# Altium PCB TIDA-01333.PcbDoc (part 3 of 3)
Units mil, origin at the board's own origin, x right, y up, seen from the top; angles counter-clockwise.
Board outline 6250 x 2150 mil, 4 copper layers (Top Layer, GND, VDD, Bottom Layer), stack 61.6 mil thick; 242 components, 144 nets, 711 pads, 252 vias.
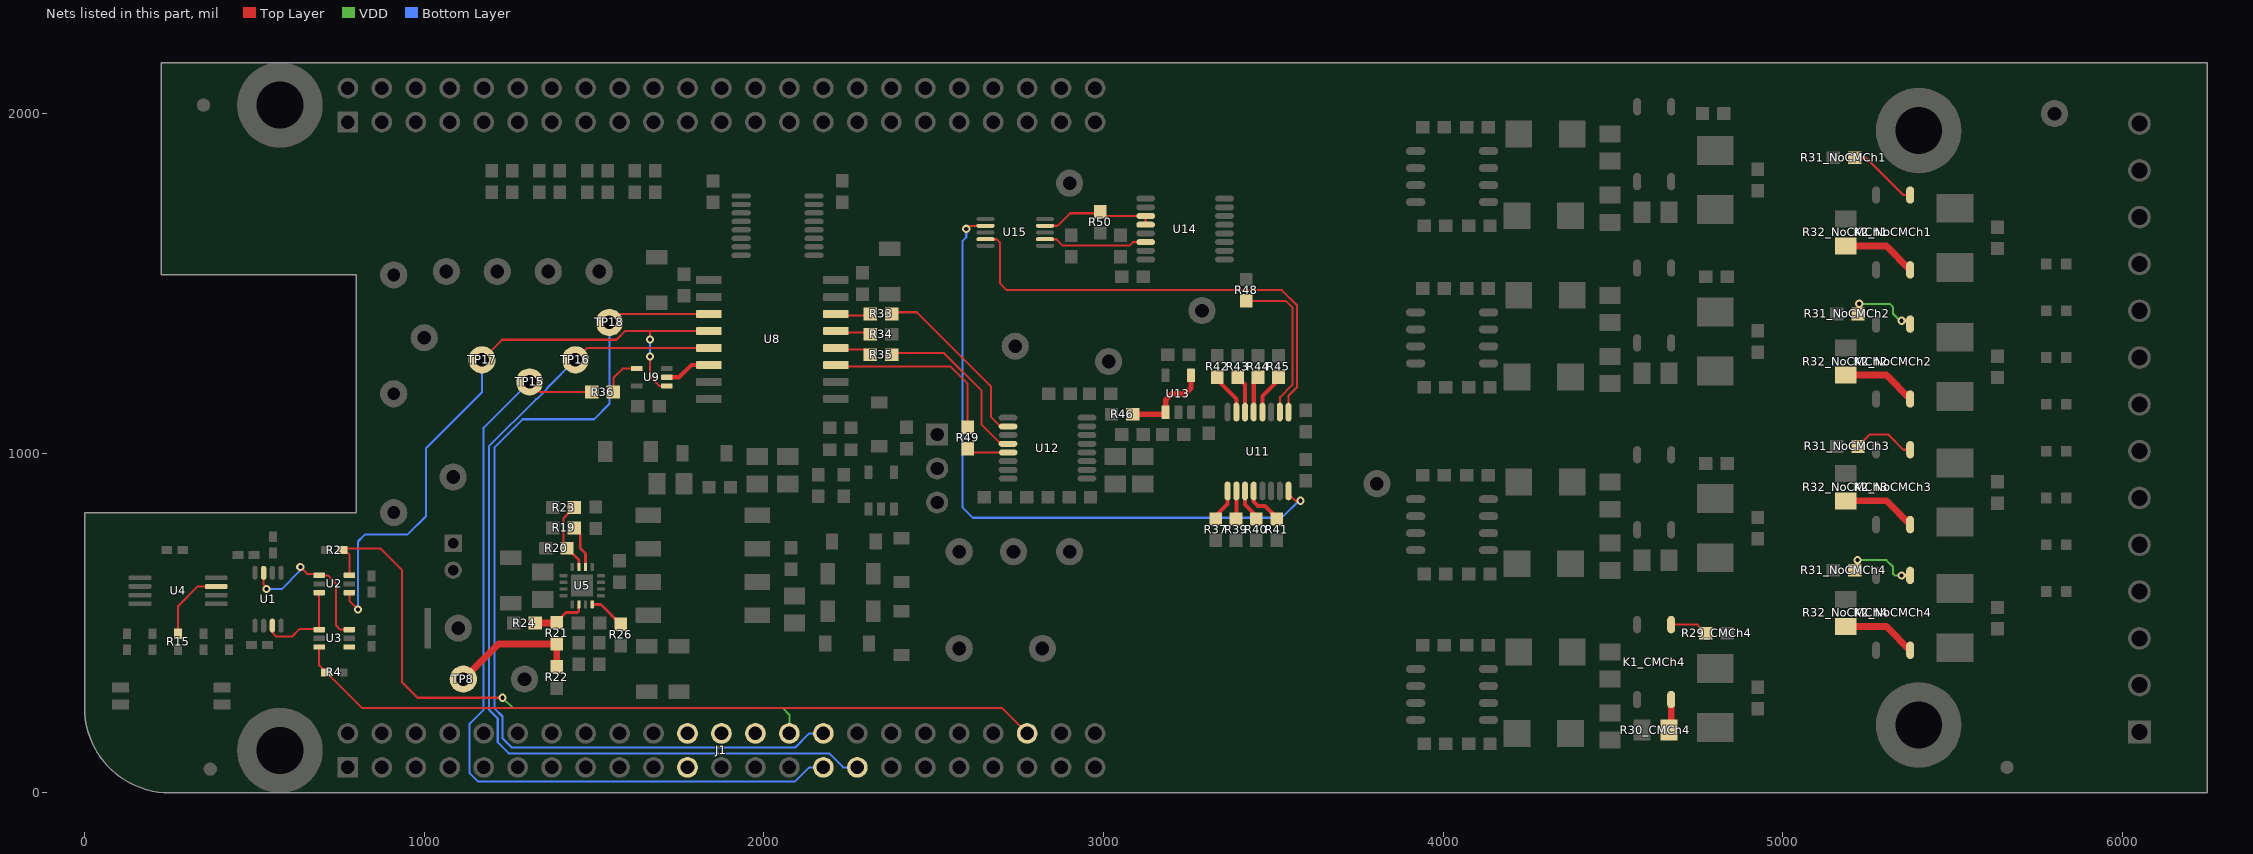
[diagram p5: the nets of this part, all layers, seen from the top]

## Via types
v1: diameter 24, hole 12, Top Layer to Bottom Layer, 210 vias
v2: diameter 39.37, hole 19.68, Top Layer to Bottom Layer, 24 vias
v3: diameter 32, hole 20, Top Layer to Bottom Layer, 17 vias
v4: diameter 19.68, hole 7.87, Top Layer to Bottom Layer, 1 vias

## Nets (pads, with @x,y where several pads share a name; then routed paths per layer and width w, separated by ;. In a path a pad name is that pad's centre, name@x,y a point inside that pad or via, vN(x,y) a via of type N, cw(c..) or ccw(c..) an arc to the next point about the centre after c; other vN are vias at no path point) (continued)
NetK1_CMCh4_1: K1_CMCh4.1 R29_CMCh4.1 | length 112.7
  Top Layer w6: K1_CMCh4.1@4671.26,495.24 4748.27,495.24 R29_CMCh4.1@4773.5,470
NetK1_CMCh4_4: K1_CMCh4.4 R30_CMCh4.2 | length 93.9
  Top Layer w20: R30_CMCh4.2@4661.26,185 4671.26,195 K1_CMCh4.4@4671.26,274.76
NetK2_NoCMCh1_1: K2_NoCMCh1.1 R31_NoCMCh1.1 | length 209
  Top Layer w6: R31_NoCMCh1.1@5211.5,1870 5245,1870 5354.76,1760.24 K2_NoCMCh1.1@5375,1760.24
NetK2_NoCMCh1_4: K2_NoCMCh1.4 R32_NoCMCh1.2 | length 219.1
  Top Layer w20: R32_NoCMCh1.2@5185,1610 5304.76,1610 K2_NoCMCh1.4@5375,1539.76
NetK2_NoCMCh2_1: K2_NoCMCh2.1 R31_NoCMCh2.1 | length 217.9
  Top Layer w6: R31_NoCMCh2.1@5221.5,1410 5221.5,1436.5 v1(5225,1440) ; v1(5350,1390) 5365.24,1390 K2_NoCMCh2.1@5375,1380.24
  VDD w6: v1(5225,1440) 5315,1440 5325,1430 5325,1410 5345,1390 v1(5350,1390)
NetK2_NoCMCh2_4: K2_NoCMCh2.4 R32_NoCMCh2.2 | length 219.1
  Top Layer w20: R32_NoCMCh2.2@5185,1230 5304.76,1230 K2_NoCMCh2.4@5375,1159.76
NetK2_NoCMCh3_1: K2_NoCMCh3.1 R31_NoCMCh3.1 | length 186.5
  Top Layer w6: R31_NoCMCh3.1@5221.5,1020 5256.5,1055 5310,1055 5354.76,1010.24 K2_NoCMCh3.1@5375,1010.24
NetK2_NoCMCh3_4: K2_NoCMCh3.4 R32_NoCMCh3.2 | length 219.1
  Top Layer w20: R32_NoCMCh3.2@5185,860 5304.76,860 K2_NoCMCh3.4@5375,789.76
NetK2_NoCMCh4_1: K2_NoCMCh4.1 R31_NoCMCh4.1 | length 219
  Top Layer w6: R31_NoCMCh4.1@5211.5,655 5220,663.5 v1(5220,685) ; v1(5350,640) 5374.76,640 K2_NoCMCh4.1@5375,640.24
  VDD w6: v1(5220,685) 5305,685 5325,665 5325,645 5330,640 v1(5350,640)
NetK2_NoCMCh4_4: K2_NoCMCh4.4 R32_NoCMCh4.2 | length 219.1
  Top Layer w20: R32_NoCMCh4.2@5185,490 5304.76,490 K2_NoCMCh4.4@5375,419.76
NetR15_2: R15.2 U4.3 | length 217.5
  Top Layer w6: R15.2@275.01,468.64 275.01,550.01 332.8,607.8 U4.3@387.2,607.8
NetR19_1: R19.1 U5.14 | length 129.1
  Top Layer w8: R19.1@1440.4,780 1458.9,761.5 1458.9,720.43 1474.84,704.49 U5.14@1474.84,665.12
NetR20_1: R20.1 R23.2 U5.15 | length 206.6
  Top Layer w6: R20.1@1420.4,720 1410,730.4 1410,808.5 R23.2@1441.5,840
  Top Layer w8: R20.1@1420.4,720 1455.16,685.24 U5.15@1455.16,665.12
NetR21_1: R21.1 R22.1 TP8.1 | length 384.9
  Top Layer w20: TP8.1@1115,335 1218.5,438.5 R21.1@1390,438.5 R22.1@1390,371.5
NetR21_2: R21.2 R24.2 U5.6 | length 162.9
  Top Layer w8: R21.2@1388.9,502.99 1417.11,531.2 1451.2,531.2 1455.16,535.16 U5.6@1455.16,554.88
  Top Layer w20: R24.2@1326.5,500 1385.91,500 R21.2@1388.9,502.99
NetR26_2: R26.2 U5.8 | length 108.3
  Top Layer w8: U5.8@1494.53,554.88 1519.96,554.88 R26.2@1578.55,496.3
NetR33_1: R33.1 U8.14 | length 107.7
  Top Layer w6: U8.14@2212.01,1410 2217.01,1405 R33.1@2303.5,1405 ; R33.1@2303.5,1400 R33.1@2313.5,1410
NetR34_1: R34.1 U8.13 | length 103.6
  Top Layer w6: U8.13@2212.01,1360 2217.01,1355 R34.1@2313.5,1355
NetR35_1: R35.1 U8.12 | length 107.7
  Top Layer w6: U8.12@2212.01,1310 2217.01,1305 R35.1@2303.5,1305 ; R35.1@2303.5,1300 R35.1@2313.5,1290
NetR36_2: R36.2 U9.4 | length 122.2
  Top Layer w6: R36.2@1556.5,1180 1556.5,1221.5 1584.27,1249.27 U9.4@1625.71,1249.27
NetR37_1: R37.1 U11.9 | length 97
  Top Layer w12: R37.1@3330,806.5 3330,815 3365.43,850.43 U11.9@3365.43,888.86
NetR39_1: R39.1 U11.10 | length 82.8
  Top Layer w12: R39.1@3390,806.5 3391.02,807.52 U11.10@3391.02,888.86
NetR40_1: R40.1 U11.11 | length 96.2
  Top Layer w12: U11.11@3416.61,888.86 3416.61,848.39 3450,815 R40.1@3450,806.5
NetR41_1: R41.1 U11.12 | length 122.2
  Top Layer w12: U11.12@3442.2,888.86 3442.2,857.8 3455,845 3475,845 3510,810 R41.1@3510,806.5
NetR42_1: R42.1 U11.7 | length 125.6
  Top Layer w12: R42.1@3335,1223.5 3335,1215 3391.02,1158.98 U11.7@3391.02,1121.14
NetR43_1: R43.1 U11.6 | length 111.3
  Top Layer w12: R43.1@3395,1223.5 3416.61,1201.89 U11.6@3416.61,1121.14
NetR44_1: R44.1 U11.5 | length 107.7
  Top Layer w12: U11.5@3442.2,1121.14 3442.2,1210.71 R44.1@3455,1223.5
NetR45_1: R45.1 U11.4 | length 121.9
  Top Layer w12: U11.4@3467.8,1121.14 3467.8,1167.8 3515,1215 R45.1@3515,1223.5
NetR46_2: R46.2 U13.1 U13.4 | length 255.8
  Top Layer w16: R46.2@3091.5,1115 3176.73,1115 U13.1@3182.6,1120.87 3182.6,1157.28 3200.31,1175 3239.68,1175 3257.4,1192.72 U13.4@3257.4,1229.13
NetR48_1: R48.1 U11.2 | length 468.9
  Top Layer w6: R48.1@3420,1448.5 3536.88,1448.5 3556.13,1429.25 3556.13,1201.13 3520,1165 3520,1120.39 U11.2@3519.29,1119.68
NetR49_2: R49.2 U12.13 | length 123.5
  Top Layer w6: R49.2@2600,1013.5 2611.3,1002.2 U12.13@2718.86,1002.2
NetR50_1: R50.1 U14.11 U14.12 U15.9 | length 333.4
  Top Layer w6: U15.9@2827.6,1669.69 2864.69,1669.69 2901.5,1706.5 R50.1@2985,1706.5 ; R50.1@2990,1701.5 2993.11,1698.39 U14.11@3123.86,1698.39 U14.12@3123.86,1672.8
NetU1_3: U1.3 U2.3 U3.1 | length 282.2
  Top Layer w6: U1.3@552.8,492.37 552.8,472.33 565,460.13 610.58,460.13 633.45,483 688.46,483 690.72,480.73 U2.3@690.72,589.52
NetU1_7: U1.7 U2.1 U3.6 | length 478.7
  Top Layer w6: U1.7@527.2,647.76 527.2,612.8 535,605 v1(535,600) ; v1(635,665) 655.13,644.87 690.71,644.87 U2.1@690.71,640.59 715.49,640.61 740.02,616.08 740.02,493.62 753.03,480.61 U3.6@779.31,480.61
  Bottom Layer w6: v1(535,600) 579.98,600 635,655.01 v1(635,665)
NetU8_6: U8.6 U9.2 | length 138.7
  Top Layer w12: U9.2@1714.29,1223.68 1750,1223.68 1786.32,1260 U8.6@1837.99,1260
NetU11_1: U11.1 U15.4 | length 1395
  Top Layer w6: U15.4@2652.09,1629.68 2652.09,1630 2685,1630 2695,1620 2695,1500 2715,1480 3525,1480 3570,1435 3570,1195 3544.88,1169.88 U11.1@3544.88,1119.68
NetU11_16: U11.16 U15.2 | length 1958.5
  Top Layer w6: v1(2595.75,1660.75) 2604.06,1669.06 U15.2@2652.09,1669.06 ; U11.16@3545,880 3565,860 v1(3580,860)
  Bottom Layer w6: v1(2595.75,1660.75) 2595.75,1635.75 2585,1625 2585,840 2615,810 3525,810 v1@3580,865
NetU14_14: U14.14 U15.7 | length 308.3
  Top Layer w6: U15.7@2827.91,1630 2861.18,1630 2880.24,1610.94 3075.94,1610.94 3086.61,1621.61 U14.14@3123.86,1621.61
SCLK_ISO: R35.2 U12.12 | length 532.3
  Top Layer w6: R35.2@2376.5,1295 2530,1295 2640,1185 2640,1085.64 2691.98,1033.65 2713,1033.65 U12.12@2718.86,1027.8 U12.12@2697.84,1027.8
SDI_ISO: R33.2 U12.10 | length 534.3
  Top Layer w6: R33.2@2376.5,1415 2450,1415 2668.87,1196.13 2668.87,1106.13 2696.02,1078.98 U12.10@2718.86,1078.98
SDO1_ISO: R49.1 U8.11 | length 539.3
  Top Layer w6: U8.11@2212.01,1260 2217.01,1255 2550,1255 2600,1205 R49.1@2600,1076.5
SPI_A: J1.28 R2.2 U2.6 | length 1834.5
  Top Layer w6: R2.2@766.51,715.01 779.31,702.22 U2.6@779.29,640.59 ; R2.2@771.51,720.01 869.98,720.01 935,655 935,325 980,280 v1(1230,280)
  VDD w6: v1(1230,280) 1260,250 2055,250 2075,230 J1.28@2075,175
SPI_B: J1.42 R4.2 U3.3 | length 2228.2
  Top Layer w6: U3.3@695.72,424.42 U3.3@690.72,429.42 690.72,375.65 R4.2@711.38,355 816.38,250 2700,250 J1.42@2775,175
SPI_CLK: J1.31 TP16.1 U8.5 | length 2740.7
  Top Layer w6: TP16.1@1445,1275 1480,1310 U8.5@1837.99,1310
  Bottom Layer w6: TP16.1@1445,1275 1445,1274.62 1360.87,1190.49 1360.87,1188.93 1331.07,1159.13 1329.51,1159.13 1190.38,1020 1190,1020 1190,245.38 1216.39,218.99 1216.39,148.61 1248.61,116.39 2192.14,116.39 2233.53,75 J1.31@2275,75
SPI_CSA: TP17.1 U2.4 U8.4 U9.1 | length 1918.1
  Top Layer w6: U2.4@779.29,589.41 779.29,565.71 v1(805,540) ; TP17.1@1170,1275 1229.13,1334.13 1566.07,1334.13 1591.95,1360 1665,1360 ; v1(1665,1285) 1665,1225 1691.91,1198.09 U9.1@1714.29,1198.09 ; v1(1665,1335) 1665,1360 ; U8.4@1837.99,1360 1665,1360
  Bottom Layer w6: v1(805,540) 805,740 825,760 950,760 1005,815 1005,1015 1170,1180 TP17.1@1170,1275 ; v1(1665,1285) v1(1665,1335)
SPI_CSB: U3.4
SPI_MISO: J1.29 R36.1 TP15.1 | length 2489.7
  Top Layer w6: TP15.1@1310,1210 1340,1180 R36.1@1493.5,1180
  Bottom Layer w6: TP15.1@1310,1210 1175,1075 1175,245 1133.61,203.61 1133.61,57.86 1157.86,33.61 2092.14,33.61 2133.53,75 J1.29@2175,75
SPI_MOSI: J1.30 TP18.1 U8.3 | length 2773
  Top Layer w6: TP18.1@1545,1385 1570,1410 U8.3@1837.99,1410
  Bottom Layer w6: TP18.1@1545,1385 1545,1145 1500,1100 1290,1100 1207.13,1017.13 1207.13,247.87 1230.26,224.74 1230.26,161.21 1257.86,133.61 2092.14,133.61 2133.53,175 J1.30@2175,175
UART_RXD1: J1.26
UART_RXD2: J1.22
UART_TXD1: J1.24
UART_TXD2: J1.21
pads on no net: FID1.1 FID2.1 FID3.1 J1.9 J1.10 J1.11 J1.12 J1.13 J1.14 J1.15 J1.16 J1.17 J1.18 J1.23 J1.25 J1.27 J1.32 J1.33 J1.34 J1.35 J1.36 J1.37 J1.38 J1.39 J1.40 J1.41 J2.3 J2.4 J2.5 J2.6 J2.7 J2.8 J2.9 J2.10 J2.13 J2.14 J2.19 J2.20 J2.21 J2.22 J2.23 J2.24 J2.25 J2.26 J2.31 J2.32 J2.33 J2.34 J2.35 J2.36 J2.37 J2.38 J2.39 J2.40 J2.41 J2.42 J2.43 J2.44 J2.45 J2.46 MH1.1 MH2.1 MH3.1 MH4.1 SH-J1.0 T1.3 U5.17@1465,610 U7_CMCh1.8 U7_CMCh2.8 U7_CMCh3.8 U7_CMCh4.8 U10.7 U12.14 U12.15 U14.9
copper on no net: | length 103920.8
  Top Layer w1: 10399.86,6070.32 10499.54,6170 10619.54,6290 10739.54,6410 10859.54,6530 10979.54,6650 11099.54,6770 11219.54,6890 11339.54,7010 11459.54,7130 11519.54,7190 ; 10399.86,6130.32 10439.54,6170 10559.54,6290 10679.54,6410 10799.54,6530 10919.54,6650 11039.54,6770 11159.54,6890 11279.54,7010 11399.54,7130 11519.54,7250 ; 10399.86,6190.32 10499.54,6290 10619.54,6410 10739.54,6530 10859.54,6650 10979.54,6770 11099.54,6890 11219.54,7010 11339.54,7130 11459.54,7250 11519.54,7310 ; 10399.86,6250.32 10439.54,6290 10559.54,6410 10679.54,6530 10799.54,6650 10919.54,6770 11039.54,6890 11159.54,7010 11279.54,7130 11399.54,7250 11519.54,7370 ; 10399.86,6310.32 10499.54,6410 10619.54,6530 10739.54,6650 10859.54,6770 10979.54,6890 11099.54,7010 11219.54,7130 11339.54,7250 11459.54,7370 ; 10399.86,6370.32 10439.54,6410 10559.54,6530 10679.54,6650 10799.54,6770 10919.54,6890 11039.54,7010 11159.54,7130 11279.54,7250 11399.54,7370 ; 10399.86,6430.32 10499.54,6530 10619.54,6650 10739.54,6770 10859.54,6890 10979.54,7010 11099.54,7130 11219.54,7250 11339.54,7370 ; 10399.86,6490.32 10439.54,6530 10559.54,6650 10679.54,6770 10799.54,6890 10919.54,7010 11039.54,7130 11159.54,7250 11279.54,7370 ; 10399.86,6550.32 10499.54,6650 10619.54,6770 10739.54,6890 10859.54,7010 10979.54,7130 11099.54,7250 11219.54,7370 ; 10399.86,6610.32 10439.54,6650 10559.54,6770 10679.54,6890 10799.54,7010 10919.54,7130 11039.54,7250 11159.54,7370 ; 10399.86,6670.32 10499.54,6770 10619.54,6890 10739.54,7010 10859.54,7130 10979.54,7250 11099.54,7370 ; 10399.86,6730.32 10439.54,6770 10559.54,6890 10679.54,7010 10799.54,7130 10919.54,7250 11039.54,7370 ; 10399.86,6790.32 10499.54,6890 10619.54,7010 10739.54,7130 10859.54,7250 10979.54,7370 ; 10399.86,6850.32 10439.54,6890 10559.54,7010 10679.54,7130 10799.54,7250 10919.54,7370 ; 10399.86,6910.32 10499.54,7010 10619.54,7130 10739.54,7250 10859.54,7370 ; 10399.86,6970.32 10439.54,7010 10559.54,7130 10679.54,7250 10799.54,7370 ; 10399.86,7030.32 10499.54,7130 10619.54,7250 10739.54,7370 ; 10399.86,7090.32 10439.54,7130 10559.54,7250 10679.54,7370 ; 10399.86,7150.32 10499.54,7250 10619.54,7370 ; 10399.86,7210.32 10439.54,7250 10559.54,7370 ; 10399.86,7270.32 10499.54,7370 ; 10399.86,7330.32 10439.54,7370 ; 10439.54,6050 10559.54,6170 10679.54,6290 10799.54,6410 10919.54,6530 11039.54,6650 11159.54,6770 11279.54,6890 11399.54,7010 11519.54,7130 ; 10499.54,6050 10619.54,6170 10739.54,6290 10859.54,6410 10979.54,6530 11099.54,6650 11219.54,6770 11339.54,6890 11459.54,7010 11519.54,7070 ; 10559.54,6050 10679.54,6170 10799.54,6290 10919.54,6410 11039.54,6530 11159.54,6650 11279.54,6770 11399.54,6890 11519.54,7010 ; 10619.54,6050 10739.54,6170 10859.54,6290 10979.54,6410 11099.54,6530 11219.54,6650 11339.54,6770 11459.54,6890 11519.54,6950 ; 10679.54,6050 10799.54,6170 10919.54,6290 11039.54,6410 11159.54,6530 11279.54,6650 11399.54,6770 11519.54,6890 ; 10739.54,6050 10859.54,6170 10979.54,6290 11099.54,6410 11219.54,6530 11339.54,6650 11459.54,6770 11519.54,6830 ; 10799.54,6050 10919.54,6170 11039.54,6290 11159.54,6410 11279.54,6530 11399.54,6650 11519.54,6770 ; 10859.54,6050 10979.54,6170 11099.54,6290 11219.54,6410 11339.54,6530 11459.54,6650 11519.54,6710 ; 10919.54,6050 11039.54,6170 11159.54,6290 11279.54,6410 11399.54,6530 11519.54,6650 ; 10979.54,6050 11099.54,6170 11219.54,6290 11339.54,6410 11459.54,6530 11519.54,6590 ; 11039.54,6050 11159.54,6170 11279.54,6290 11399.54,6410 11519.54,6530 ; 11099.54,6050 11219.54,6170 11339.54,6290 11459.54,6410 11519.54,6470 ; 11159.54,6050 11279.54,6170 11399.54,6290 11519.54,6410 ; 11219.54,6050 11339.54,6170 11459.54,6290 11519.54,6350 ; 11279.54,6050 11399.54,6170 11519.54,6290 ; 11339.54,6050 11459.54,6170 11519.54,6230 ; 11399.54,6050 11519.54,6170 ; 11459.54,6050 11519.54,6110
  Top Layer w15: 6980.74,6170 7390.65,6170 8320.4,6170 9180.16,6170 9830,6170 10399.86,6170 11519.54,6170 ; 6980.74,6290 7390.65,6290 8320.4,6290 9180.16,6290 9830,6290 10399.86,6290 11519.54,6290 ; 6980.74,6410 7390.65,6410 8320.4,6410 9180.16,6410 9830,6410 10399.86,6410 11519.54,6410 ; 6980.74,6530 7390.65,6530 8320.4,6530 9180.16,6530 9830,6530 10399.86,6530 11519.54,6530 ; 6980.74,6650 7390.65,6650 8320.4,6650 9180.16,6650 9830,6650 10399.86,6650 11519.54,6650 ; 6980.74,6770 7390.65,6770 8320.4,6770 9180.16,6770 9830,6770 10399.86,6770 11519.54,6770 ; 6980.74,6890 7390.65,6890 8320.4,6890 9180.16,6890 9830,6890 10399.86,6890 11519.54,6890 ; 6980.74,7010 7390.65,7010 8320.4,7010 9180.16,7010 9830,7010 10399.86,7010 11519.54,7010 ; 6980.74,7130 7390.65,7130 8320.4,7130 9180.16,7130 9830,7130 10399.86,7130 11519.54,7130 ; 6980.74,7250 7390.65,7250 8320.4,7250 9180.16,7250 9830,7250 10399.86,7250 11519.54,7250 ; 6980.74,7370 11519.54,7370 ; 7390.65,7490 7390.65,6050 ; 8320.4,7490 8320.4,6050 ; 9180.16,7490 9180.16,6050 ; 9830,7490 9830,6050 ; 10399.86,7490 10399.86,6050 ; 7390.65,6050 8320.4,6050 ; 7390.65,6050 6980.74,6050 6980.74,7490 11519.54,7490 11519.54,6050 10399.86,6050 ; 8320.4,6050 9180.16,6050 ; 9180.16,6050 9830,6050 ; 9830,6050 10399.86,6050
  other v2: 575,27.56 490.61,76.28 659.39,76.28 5400,102.56 5315.61,151.28 5484.39,151.28 490.61,173.72 659.39,173.72 575,222.44 5315.61,248.72 5484.39,248.72 5400,297.44 5400,1852.56 5315.61,1901.28 5484.39,1901.28 575,1927.56 490.61,1976.28 659.39,1976.28 5315.61,1998.72 5484.39,1998.72 5400,2047.44 490.61,2073.72 659.39,2073.72 575,2122.44

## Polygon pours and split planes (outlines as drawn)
GND_ISO on GND "GND_ISO_L02_P045" (solid, remove dead copper, pour order 45): 2025,2150 2025,1075 1605,1075 1605,690 1825,690 1825,0 6255,0 6255,2150
DGND on GND "DGND" (solid, pour order 39): 0,250 0,825 800,825 800,1525 225,1525 225,2150 2025,2150 3100,2150 3100,1900 2025,1900 2025,1075 1605,1075 1605,700 1800,700 1800,250 3100,250 3100,0 1825,0 250,0 cw(c250,250)
+5V_ISO on VDD "+5V_ISO_L03_P049" (solid, pour order 49): 1615,750 2670,750 2735,770 2800,750 3100,750 ccw(c3100,800) 3150,800 3150,1400 cw(c3200,1400) 3200,1450 3400,1450 ccw(c3400,1500) 3450,1500 3450,1825 ccw(c3400,1825) 3400,1875 2025,1875 2025,1070 1615,1070
+5V on VDD "+5V_L03_P065" (solid, remove dead copper, pour order 65): 1150,300 1030,420 1030,1900 2000,1900 2000,1100 1580,1100 1580,700 1800,700 1800,300
DVDD on VDD "+5V" (solid, pour order 47): 0,250 0,825 830,825 830,1650 980,1650 980,250 3100,250 3100,0 990,0 250,0 cw(c250,250)
-15V_ISO on VDD "-15V_ISO_L03_P051" (solid, remove dead copper, pour order 51): 2265,660 2265,580 4025,580 4025,2025 3975,2025 3975,660
+15V_ISO on VDD "+15V_ISO_L03_P053" (solid, remove dead copper, pour order 53): 2216.52,555 2216.52,480 4051.52,480 4051.52,81.71 4100,81.71 4100,1671.71 4051.52,1671.71 4051.52,555
+5V_ISO on Top Layer "+5V_ISO_L01_P079" (solid, pour order 79): 2185,1500 2245,1500 2260,1500 2270,1510 2325,1510 2335,1520 2335,1555 2344.99,1564.99 2425,1564.99 2435,1574.99 2435,1620 2425,1630 2330.43,1630 2310.43,1610 2275.47,1574.99 2260,1559.57 2220.43,1520 2185,1520
-15V_ISO on Top Layer "-15V_ISO_L01_P069" (solid, pour order 69): 3100,630 3178.89,706.11 3195,690 3195,615 3105,615
+5V on Top Layer "+5V_L01_P057" (solid, pour order 57): 1308.9,625 1383.9,625 1393.9,615 1403.9,615 1413.9,615 1418.9,620 1418.9,650 1423.9,655 1438.9,655 1438.9,675 1433.9,680 1423.9,690 1393.9,690 1388.9,695 1388.9,795 1333.9,795 1328.9,790 1328.9,715 1323.9,710 1223.9,710
+15V_ISO on Top Layer "+15V_ISO_L01_P067" (solid, pour order 67): 3200,540.25 3235.02,565.02 3254.62,565.02 3290,540 3290,520 3290,510.04 3200,510.04
DGND on Top Layer "DGND_L01_P059" (solid, pour order 59): 1444.87,606.38 1299.87,606.38 1289.87,596.38 1219.87,596.38 1219.87,551.38 1439.87,551.38 1439.87,571.38 1444.87,576.38 1454.87,576.38 1454.87,596.38
+15V_ISO on Top Layer "+15V_ISO_L01_P073" (solid, pour order 73): 2285,570 2285,465 2285,410 2330,410 2330,475 2485,475 2495,485 2495,540 2475,560 2345,560 2345,570
-15V_ISO on Top Layer "-15V_ISO_L01_P075" (solid, pour order 75): 2295,765 2295,580 2475,580 2495,600 2495,640 2475,660 2350,660 2350,765
NetC10_1 on Top Layer "NETC10_1_L01_P077" (solid, remove dead copper, pour order 77): 1508.88,645 1535,645 1540,640 1695,640 1695,600 1540,600 1535,595 1508.75,595
+5V on Top Layer "+5V_L01_P081" (solid, pour order 81): 1747.4,1500 1722.4,1525 1745,1502.4 1745,1500 1745,1505 1715,1535 1660,1535 1630,1565 1625,1570 1625,1610 1640.86,1625.86 1714.14,1625.86 1805,1535 1805,1500
DGND on Bottom Layer "DGND_L04_P071" (solid, pour order 71): 1180,420 1330,270 1765,270 1800,305 1800,700 1580,700 1580,880 1555,905 1205,905 1180,880

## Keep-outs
Keep-Out Layer:
  lines w10: 800,825 800,1525 225,1525 225,2150 6250,2150 6250,0 250,0 cw(c250,250) 0,250 0,825 800,825 ; 800,825 800,825
  text ".Layer_Name" at 577,-858.49 h60

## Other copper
Top Layer:
  text "Layer" at 7040.74,7400 h60
  text "Name" at 7450.65,7400 h60
  text "Material" at 8380.4,7400 h60
  text "Thickness" at 9240.16,7400 h60
  text "Constant" at 9890,7400 h60
  text "Board Layer Stack" at 10459.86,7400 h60
  text "1" at 7040.74,7280 h60
  text "Top Overlay" at 7450.65,7280 h60
  text "2" at 7040.74,7160 h60
  text "Top Solder" at 7450.65,7160 h60
  text "Solder Resist" at 8380.4,7160 h60
  text "0,40mil" at 9240.16,7160 h60
  text "3,5" at 9890,7160 h60
  text "3" at 7040.74,7040 h60
  text "Top Layer" at 7450.65,7040 h60
  text "Copper" at 8380.4,7040 h60
  text "1,40mil" at 9240.16,7040 h60
  text "4" at 7040.74,6920 h60
  text "Dielectric 1" at 7450.65,6920 h60
  text "8,00mil" at 9240.16,6920 h60
  text "4,2" at 9890,6920 h60
  text "5" at 7040.74,6800 h60
  text "GND" at 7450.65,6800 h60
  text "Copper" at 8380.4,6800 h60
  text "1,40mil" at 9240.16,6800 h60
  text "6" at 7040.74,6680 h60
  text "Dielectric 2" at 7450.65,6680 h60
  text "FR-4" at 8380.4,6680 h60
  text "40,00mil" at 9240.16,6680 h60
  text "4,2" at 9890,6680 h60
  text "7" at 7040.74,6560 h60
  text "VDD" at 7450.65,6560 h60
  text "Copper" at 8380.4,6560 h60
  text "1,40mil" at 9240.16,6560 h60
  text "8" at 7040.74,6440 h60
  text "Dielectric 3" at 7450.65,6440 h60
  text "8,00mil" at 9240.16,6440 h60
  text "4,2" at 9890,6440 h60
  text "9" at 7040.74,6320 h60
  text "Bottom Layer" at 7450.65,6320 h60
  text "Copper" at 8380.4,6320 h60
  text "1,40mil" at 9240.16,6320 h60
  text "10" at 7040.74,6200 h60
  text "Bottom Solder" at 7450.65,6200 h60
  text "Solder Resist" at 8380.4,6200 h60
  text "0,40mil" at 9240.16,6200 h60
  text "3,5" at 9890,6200 h60
  text "11" at 7040.74,6080 h60
  text "Bottom Overlay" at 7450.65,6080 h60
  text ".Layer_Name" at 577,-858.49 h60
GND:
  pour cut-out: 1580,700 1580,750 1849.85,750 1849.85,700
  pour cut-out: 1630,700 1580,700 1580,1100 1630,1100
  pour cut-out: 2050,1100 2050,1050 1580,1050 1580,1100
  pour cut-out: 1800,750 1850,750 1850,250 1800,250
  pour cut-out: 2000,1924 2050,1924 2050,1050 2000,1050
  pour cut-out: 3100,300 3150,300 3150,0 3100,0
  pour cut-out: 1800,250 1800,300 3150,300 3150,250
  pour cut-out: 2000,1875 2000,1925 3150,1925 3150,1875
  pour cut-out: 3100,2150 3150,2150 3150,1900 3100,1900
VDD:
  pour cut-out: 1800,750 1850,750 1850,250 1800,250
  pour cut-out: 1580,700 1580,750 1849.85,750 1849.85,700
  pour cut-out: 1630,700 1580,700 1580,1100 1630,1100
  pour cut-out: 2050,1100 2050,1050 1580,1050 1580,1100
  pour cut-out: 2000,1923.44 2050,1923.44 2050,1050 2000,1050
  pour cut-out: 1800,250 1800,300 3150,300 3150,250
  pour cut-out: 3100,300 3150,300 3150,0 3100,0
  pour cut-out: 2000,1875 2000,1925 3150,1925 3150,1875
  pour cut-out: 3100,2150 3150,2150 3150,1900 3100,1900
Bottom Layer:
  text ".Layer_Name" at 577,-858.49 h60

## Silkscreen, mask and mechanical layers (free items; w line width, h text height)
Top Overlay:
  lines w10: 1595,895 1595,725 1610,725 ; 1600,1060 1600,1075 1725,1075 ; 1715,725 1831.3,725 ; 1830,265 1830,305 ; 1830,430 1830,725
  text "_RCLK" at 2705,1835 h30
  text "CMCh1" at 4195,1785 h80
  text "MUX_out" at 3035,1440 h30
  text "NoCMCh1" at 5260,1440 h80
  text "IN1+2" at 1000,1435 h30
  text "A0" at 1190,1435 h30
  text "A1" at 1345,1435 h30
  text "A2" at 1440,1435 h30
  text "GND" at 870,1430 h30
  text "MOSI" at 1615,1370 h30
  text "ADC_in" at 2850,1345 h30
  text "CMCh2" at 4195,1320 h80
  text "CLK" at 1515,1260 h30
  text "CS" at 1060,1210 h30
  text "MISO" at 1140,1155 h30
  text "VDD" at 870,1075 h30
  text "NoCMCh2" at 5260,1060 h80
  text "off" at 2570,935 h72.83
  text "+5V" at 1160,920 h30
  text "EN" at 2610,850 h60 r90
  text "on" at 2570,795 h72.83
  text "CMCh3" at 4195,775 h80
  text "GND" at 870,735 h30
  text "AVDD" at 2980,690 h30
  text "NoCMCh3" at 5260,690 h80
  text "-15V_iso |" at 2520,570 h30
  text "+5V_iso" at 2805,565 h30
  text "CAPE-ID AND" at 945,320 h30 r90
  text "ADDR-DEC" at 990,320 h30 r90
  text "NoCMCh4" at 5535,295 h80
  text "+15V_iso" at 2520,285 h30
  text "CMCh4" at 4195,270 h80
  text ".Layer_Name" at 577,-858.49 h30
Bottom Overlay:
  text ".Layer_Name" at 577,-858.49 h60
Top Paste:
  text ".Layer_Name" at 577,-858.49 h60
Bottom Paste:
  text ".Layer_Name" at 577,-858.49 h60
Top Solder:
  text ".Layer_Name" at 577,-858.49 h60
  text ".Layer_Name" at 577,-858.49 h60
Bottom Solder:
  text ".Layer_Name" at 577,-858.49 h60
Drill Guide:
  text ".Layer_Name" at 577,-858.49 h60
M1 Board Outline:
  the board outline again, w10
  text ".Layer_Name" at 577,-858.49 h60
M2 Board Dimensions:
  lines w10: 5.01,-154.98 5.01,-134.98 ; 65.01,-164.98 5.01,-144.98 ; 65.01,-124.98 5.01,-144.98 ; 2849.1,-144.98 5.01,-144.98 ; 3410.93,-144.98 6255.02,-144.98 ; 5083,651 5283,651 ; 6195.02,-164.98 6255.02,-144.98 ; 6195.02,-124.98 6255.02,-144.98 ; 6255.02,-194.98 6255.02,5.02 ; 6255.02,-154.98 6255.02,-134.98 ; 6385.02,65.02 6405.02,5.02 ; 6385.02,2095.01 6405.02,2155.01 ; 6395.02,5.02 6415.02,5.02 ; 6395.02,2155.01 6415.02,2155.01 ; 6405.02,804.1 6405.02,5.02 ; 6405.02,1355.93 6405.02,2155.01 ; 6425.02,65.02 6405.02,5.02 ; 6425.02,2095.01 6405.02,2155.01
  text "2150 (mil)" at 6441.01,814.1 h60 r90
  text "6250 (mil)" at 2859.1,-180.98 h60
  text ".Layer_Name" at 577,-858.49 h60
M3 3D STEP Top:
  text ".Layer_Name" at 577,-858.49 h60
M4 3D STEP Bottom:
  text ".Layer_Name" at 577,-858.49 h60
M5 Assembly Top:
  text "COMPONENTS MARKED 'DNP' SHOULD NOT BE POPULATED." at 1153.5,-318.5 h60
  text "ASSEMBLY VARIANT:" at 1153,-434 h60
  text ".VariantName" at 2189,-434 h60
  text "PCB VIEWED FROM TOP SIDE" at -228.5,-655.67 h60
  text "BOARD #:" at 2248,-655.67 h60
  text ".PRJ_Number" at 2793.5,-655.67 h60
  text "REV:" at 3638,-655.67 h60
  text ".PCB_Rev" at 3929.5,-655.67 h60
  text "SVN REV:" at 4476,-655.67 h60
  text ".VersionControl_RevNumber" at 4982,-655.67 h60
  text "TID #:" at 2248,-859 h60
  text ".TID" at 2793.5,-859 h60
  text "PLOT NAME =" at -228.5,-1064.34 h60
  text ".plot_File_Name" at 577,-1064.34 h60
  text "GENERATED    :" at 2250,-1064.34 h60
  text ".Print_Date" at 3119.5,-1064.34 h60
  text ".Print_Time" at 3848.5,-1064.34 h60
  text "TEXAS INSTRUMENTS" at 5113,-1064.34 h60
M6 Assembly Bottom:
  text "COMPONENTS MARKED 'DNP' SHOULD NOT BE POPULATED." at 6102,-318 h60
  text ".VariantName" at 5058,-434 h60
  text "ASSEMBLY VARIANT:" at 6097,-434 h60
  text ".VersionControl_RevNumber" at 1035.5,-656.17 h60
  text "SVN REV:" at 1541.5,-656.17 h60
  text ".PCB_Rev" at 2088,-656.17 h60
  text "REV:" at 2379.5,-656.17 h60
  text ".PRJ_Number" at 3224,-656.17 h60
  text "BOARD #:" at 3769.5,-656.17 h60
  text "PCB VIEWED FROM BOTTOM SIDE" at 6246,-656.17 h60
  text ".TID" at 3224,-859.5 h60
  text "TID #:" at 3769.5,-859.5 h60
  text "TEXAS INSTRUMENTS" at 904.5,-1064.84 h60
  text ".Print_Time" at 2169,-1064.84 h60
  text ".Print_Date" at 2898,-1064.84 h60
  text "GENERATED    :" at 3767.5,-1064.84 h60
  text ".plot_File_Name" at 5440.5,-1064.84 h60
  text "PLOT NAME =" at 6246,-1064.84 h60
M9 Title Sheet:
  drawing of 18 lines, arcs and shapes, not listed
  text "1" at 739.84,8036.5 h70
  text "2" at 3235.5,8036.5 h70
  text "3" at 5724.84,8036.5 h70
  text "4" at 8231.51,8036.5 h70
  text "5" at 10730.5,8036.5 h70
  text "6" at 13235.5,8036.5 h70
  text "A" at -416.5,6893.5 h70
  text "A" at 14383.5,6893.5 h70
  text "B" at -416.5,4513.5 h70
  text "B" at 14383.5,4513.5 h70
  text "C" at -416.5,2138.5 h70
  text "C" at 14383.5,2138.5 h70
  text "PROJECT TITLE:" at 11343.5,277.5 h45
  text ".PRJ_Title" at 11393.5,144.17 h70
  text "DESIGNED FOR:" at 11343.5,-23.5 h45
  text ".PRJ_Customer" at 11393.5,-163.5 h70
  text "D" at -416.5,-231.5 h70
  text "D" at 14383.5,-231.5 h70
  text "FILE NAME:" at 11343.5,-323.5 h45
  text ".PCB_File_Name_No_Path" at 11393.5,-443.5 h70
  text "Texas Instruments (TI) and/or its licensors do not warrant the accuracy or completeness of this specification" at 6374,-605.34 h45
  text "ENGINEER:" at 11343.5,-613.5 h45
  text "LAYOUT BY:" at 12848.5,-613.5 h45
  text "or any information contained therein. TI and/or its licensors do not warrant that this design will meet" at 6329.01,-718 h45
  text ".PRJ_Engineer" at 11393.5,-768.49 h70
  text ".PCB_Layout" at 12899,-768.49 h70
  text "the specifications, will be suitable for your application or fit for any particular purpose, or will operate in" at 6329.01,-830.67 h45
  text ".Layer_Name" at 577,-858.49 h60
  text "ALTIUM DESIGNER VERSION:" at 12848.5,-923.5 h45
  text "an implementation. TI and/or its licensors do not warrant that the design is production worthy. You should" at 6329.01,-943.33 h45
  text "completely validate and test your design implementation to confirm the system functionality for your application." at 6374,-1056 h45
  text ".print_Scale" at 11393.5,-1056.83 h70
  text ".Application_BuildNumber" at 12899,-1056.83 h70
  text "1" at 739.84,-1263.5 h70
  text "2" at 3235.5,-1263.5 h70
  text "3" at 5724.84,-1263.5 h70
  text "4" at 8231.51,-1263.5 h70
  text "5" at 10730.5,-1263.5 h70
  text "6" at 13235.5,-1263.5 h70
M10 Fab Notes:
  text "DESIGN INFORMATION" at 12381.02,5910 h60
  text "MIN. TRACK WIDTH:" at 11736.46,5730 h60
  text "6" at 12832.7,5730 h60
  text "MIL" at 12987.46,5730 h60
  text "MIN. CLEARANCE:" at 11736.46,5598 h60
  text "0.2" at 12772.7,5598 h60
  text "mm" at 12987.46,5598 h60
  text "MIN. VIA PAD SIZE:" at 11736.46,5466 h60
  text "24" at 12802.71,5466 h60
  text "MIL" at 12987.46,5466 h60
  text "0.05mm (2MIL)" at 12431.46,5324.29 h60
  text "MINIMUM ANNULAR RING" at 11407.23,5320 h60
  text "EXTERNAL" at 13139.46,5320 h60
  text "PER" at 11607.23,5202 h60
  text "IPC-D-275 CLASS 2 LEVEL C" at 11827.23,5202 h60
  text "MIL, HOLES" at 13315.46,5089.71 h60
  text "+/-" at 12923,5089 h60
  text "+/-" at 13777,5089 h60
  text "REGISTRATION TOLERANCES:" at 11407.23,5084 h60
  text "METAL" at 12607,5084 h60
  text "5" at 13183.2,5084 h60
  text "3" at 14016.2,5084 h60
  text "MIL" at 14132.46,5084 h60
  text "MATERIAL:" at 11332.46,4874.54 h60
  text "FR-4 High Tg" at 12318.9,4734.21 h60
  text "FR-408" at 11753.46,4725.64 h60
  text "X" at 12165.46,4725.64 h60
  text "OTHER" at 13241.46,4725.64 h60
  text "62 MIL (1.6mm) +/-10%" at 12073.56,4562.92 h60
  text "THICKNESS:" at 11407.23,4558.64 h60
  text "X" at 11945.4,4558.64 h60
  text "OTHER" at 13358.46,4558.64 h60
  text "TOLERANCE:" at 11407.23,4400.64 h60
  text "X" at 12246.53,4400.64 h60
  text "ANSI IPC-6012 TYPE 3 CLASS 2" at 12433.48,4400.64 h60
  text "OTHER +/-" at 12433.46,4244.64 h60
  text "BOW & TWIST:" at 11407.23,4087.64 h60
  text "X" at 12246.53,4087.64 h60
  text "ANSI IPC-6012 TYPE 3 CLASS 2" at 12433.48,4087.64 h60
  text "OTHER +/-" at 12433.46,3929.13 h60
  text "DRILLING:" at 11332.46,3790.64 h60
  text "REFERENCE:" at 11407.23,3673.64 h60
  text "X" at 12055.46,3673.64 h60
  text "AS SHOWN" at 12242.46,3673.64 h60
  text "X" at 12956.46,3673.64 h60
  text "NC_DRILL FILES" at 13093.46,3673.64 h60
  text "PTH MIN COPPER THICKNESS:" at 11407.23,3515.64 h60
  text "X" at 12757.46,3515.64 h60
  text "1MIL" at 12894.46,3515.64 h60
  text "OTHER" at 13391.46,3515.64 h60
  text "BOARD FINISH:" at 11332.46,3356.64 h60
  text "SILKSCREEN:" at 11487.68,3238.64 h60
  text "X" at 12436.46,3238.64 h60
  text "TOP" at 12562.46,3238.64 h60
  text "X" at 12946.46,3238.64 h60
  text "BOTTOM" at 13073.46,3238.64 h60
  text "SILKSCREEN COLOR:" at 11487.68,3071.64 h60
  text "X" at 12435.42,3071.64 h60
  text "WHITE" at 12562.46,3071.64 h60
  text "OTHER" at 13073.46,3071.64 h60
  text "SOLDER RESIST COLOR:" at 11487.68,2901.64 h60
  text "X" at 12055.42,2742.44 h60
  text "GREEN" at 12182.46,2742.44 h60
  text "BLUE" at 12773.46,2742.44 h60
  text "OTHER" at 13311.46,2742.44 h60
  text "IMMERSION GOLD (ENIG)" at 12393.46,2553.92 h60
  text "ENEPIG" at 13731,2550.64 h60
  text "SURFACE FINISH:" at 11332.46,2549.64 h60
  text "X" at 12206.51,2549.64 h60
  text "IMM. TIN/SILVER OR EQUIV" at 11662,2392.64 h60
  text "OTHER" at 13093.46,2392.64 h60
  text "ARRAY/PANEL:" at 11332.46,2213.64 h60
  text "CUT AND TRIM PER MECH LAYER 1" at 12393.46,2209.35 h60
  text "N.C. ROUTE" at 12393.46,2057.64 h60
  text "X" at 13072.46,2057.64 h60
  text "V. SCORE" at 13259.46,2057.64 h60
  text "CERTIFICATION:" at 11332.46,1920.64 h60
  text "MATERIALS AND WORKMANSHIP FOR ALL PCBS" at 12057.46,1920.64 h60
  text "TO MEET OR EXCEED THE REQUIREMENTS OF:" at 12057.46,1822.64 h60
  text "X" at 11683.96,1686.13 h60
  text "ANSI IPC-A-600F CLASS ->" at 11822.96,1686.13 h60
  text "X" at 13462.02,1686.13 h60
  text "2" at 13580.96,1686.14 h60
  text "1" at 13265.96,1684.64 h60
  text "3" at 13934.96,1684.64 h60
  text "X" at 11686.02,1526.64 h60
  text "UL 94V-0" at 11822.96,1526.64 h60
  text "X" at 12498.02,1526.64 h60
  text "RoHS" at 12634.96,1526.64 h60
  text "OTHER" at 13279.36,1526.64 h60
  text "PER ORDER" at 13676.42,1526.64 h60
  text "ADDITIONAL REQUIREMENTS:" at 11332.46,1385.64 h60
  text "MICROSECTION:" at 11407.23,1270.64 h60
  text "YES" at 12312.96,1270.64 h60
  text "REQUIRED" at 13174.46,1114.49 h60
  text "BARE BOARD ELEC. TEST:" at 11407.23,1111.64 h60
  text "NONE" at 12712.96,1111.64 h60
  text "X" at 13047.46,1111.64 h60
  text "PER ORDER" at 13766.46,1111.64 h60
  text "MANUFACTURER'S UL:" at 11407.23,954.64 h60
  text "RAIL" at 12572.96,950.35 h60
  text "METAL" at 13064.77,950.35 h60
  text "X" at 13440,950 h60
  text "SILK" at 13576.46,950.35 h60
  text ".Layer_Name" at 577,-858.49 h60
M11 Gerber Information:
  text "ALL ARTWORK VIEWED FROM TOP SIDE" at -228.5,-655.67 h60
  text "BOARD #:" at 2248,-655.67 h60
  text ".PRJ_Number" at 2793.5,-655.67 h60
  text "REV:" at 3638,-655.67 h60
  text ".PCB_Rev" at 3929.5,-655.67 h60
  text "SVN REV:" at 4476,-655.67 h60
  text ".VersionControl_RevNumber" at 4982,-655.67 h60
  text "LAYER NAME =" at -228.5,-858.49 h60
  text "TID #:" at 2248,-859 h60
  text ".TID" at 2793.5,-859 h60
  text "PLOT NAME =" at -228.5,-1064.34 h60
  text ".plot_File_Name" at 577,-1064.34 h60
  text "GENERATED    :" at 2250,-1064.34 h60
  text ".Print_Date" at 3119.5,-1064.34 h60
  text ".Print_Time" at 3848.5,-1064.34 h60
  text "TEXAS INSTRUMENTS" at 5113,-1064.34 h60
M12 Stackup:
  text ".Layer_Name" at 577,-858.49 h60
M13 Component Bodies Top:
  text ".Layer_Name" at 577,-858.49 h60
M14 Component Bodies Bottom:
  text ".Layer_Name" at 577,-858.49 h60
M15 Courtyards Top:
  text ".Layer_Name" at 577,-858.49 h60
M16 Courtyards Bottom:
  text ".Layer_Name" at 577,-858.49 h60
Drill Drawing:
  circle w10: c4214,6682.03 r27.63
  circle w10: c4214,6184.75 r16.58
  circle w10: c4214,6184.75 r27.63
  lines w10: 4186.37,6281.44 4186.37,6295.25 4200.18,6309.07 4186.37,6322.88 4186.37,6336.69 4200.18,6336.69 4214,6322.88 4227.81,6336.69 4241.62,6336.69 4241.62,6322.88 4227.81,6309.07 4241.62,6295.25 4241.62,6281.44 4227.81,6281.44 4214,6295.25 4200.18,6281.44 4186.37,6281.44 ; 4186.37,6461.01 4241.62,6461.01 4214,6405.76 4186.37,6461.01 ; 4186.37,6543.89 4200.18,6543.89 4214,6530.08 4227.81,6543.89 4241.62,6543.89 4227.81,6557.71 4241.62,6571.52 4227.81,6571.52 4214,6585.33 4200.18,6571.52 4186.37,6571.52 4200.18,6557.71 4186.37,6543.89 ; 4186.37,6778.72 4241.62,6778.72 4241.62,6833.97 4186.37,6833.97 4186.37,6778.72 ; 4186.37,6958.29 4241.62,6958.29 4214,6903.04 4186.37,6958.29 ; 4186.37,7054.99 4214,7027.36 4241.62,7054.99 4214,7082.61 4186.37,7054.99 ; 4186.37,7151.68 4214,7165.49 4241.62,7151.68 4227.81,7179.31 4241.62,7206.93 4214,7193.12 4186.37,7206.93 4200.18,7179.31 4186.37,7151.68 ; 4186.37,7276 4241.62,7276 4241.62,7331.25 4186.37,7331.25 4186.37,7276 ; 4186.37,7414.13 4200.18,7414.13 4214,7400.32 4227.81,7414.13 4241.62,7414.13 4227.81,7427.95 4241.62,7441.76 4227.81,7441.76 4214,7455.57 4200.18,7441.76 4186.37,7441.76 4200.18,7427.95 4186.37,7414.13 ; 4197.42,6449.96 4230.57,6449.96 4214,6416.81 4197.42,6449.96 ; 4197.42,6549.42 4205.71,6549.42 4214,6541.13 4222.28,6549.42 4230.57,6549.42 4222.28,6557.71 4230.57,6565.99 4222.28,6565.99 4214,6574.28 4205.71,6565.99 4197.42,6565.99 4205.71,6557.71 4197.42,6549.42 ; 4197.42,6789.77 4230.57,6789.77 4230.57,6822.92 4197.42,6822.92 4197.42,6789.77
  lines w12: 4136.28,6119.82 6114.3,6119.82 ; 4136.28,7487.34 6114.3,7487.34 ; 4474.14,5995.5 4474.14,7611.66 ; 4806.14,5995.5 4806.14,7611.66 ; 5442.7,5995.5 5442.7,7611.66 ; 5701.84,5995.5 5701.84,7611.66 ; 4136.28,5995.5 6114.3,5995.5 6114.3,7611.66 4136.28,7611.66 4136.28,5995.5
  text "Symbol" at 4210.87,7524.64 h72
  text "Quantity" at 4511.44,7524.64 h72
  text "Finished Hole Size" at 4843.44,7524.64 h72
  text "Plated" at 5480,7524.64 h72
  text "Hole Type" at 5739.14,7524.64 h72
  text "1" at 4511.44,7400.32 h60
  text "7,87mil (0,200mm)" at 4843.44,7400.32 h60
  text "PTH" at 5480,7400.32 h60
  text "Round" at 5739.14,7400.32 h60
  text "210" at 4511.44,7276 h60
  text "12,00mil (0,305mm)" at 4843.44,7276 h60
  text "PTH" at 5480,7276 h60
  text "Round" at 5739.14,7276 h60
  text "24" at 4511.44,7151.68 h60
  text "19,69mil (0,500mm)" at 4843.44,7151.68 h60
  text "PTH" at 5480,7151.68 h60
  text "Round" at 5739.14,7151.68 h60
  text "17" at 4511.44,7027.36 h60
  text "20,00mil (0,508mm)" at 4843.44,7027.36 h60
  text "PTH" at 5480,7027.36 h60
  text "Round" at 5739.14,7027.36 h60
  text "2" at 4511.44,6903.04 h60
  text "31,00mil (0,787mm)" at 4843.44,6903.04 h60
  text "PTH" at 5480,6903.04 h60
  text "Round" at 5739.14,6903.04 h60
  text "3" at 4511.44,6778.72 h60
  text "37,99mil (0,965mm)" at 4843.44,6778.72 h60
  text "PTH" at 5480,6778.72 h60
  text "Round" at 5739.14,6778.72 h60
  text "3" at 4511.44,6654.4 h60
  text "39,37mil (1,000mm)" at 4843.44,6654.4 h60
  text "PTH" at 5480,6654.4 h60
  text "Round" at 5739.14,6654.4 h60
  text "24" at 4511.44,6530.08 h60
  text "40,00mil (1,016mm)" at 4843.44,6530.08 h60
  text "PTH" at 5480,6530.08 h60
  text "Round" at 5739.14,6530.08 h60
  text "92" at 4511.44,6405.76 h60
  text "40,16mil (1,020mm)" at 4843.44,6405.76 h60
  text "PTH" at 5480,6405.76 h60
  text "Round" at 5739.14,6405.76 h60
  text "14" at 4511.44,6281.44 h60
  text "47,24mil (1,200mm)" at 4843.44,6281.44 h60
  text "PTH" at 5480,6281.44 h60
  text "Round" at 5739.14,6281.44 h60
  text "4" at 4511.44,6157.12 h60
  text "137,80mil (3,500mm)" at 4843.44,6157.12 h60
  text "PTH" at 5480,6157.12 h60
  text "Round" at 5739.14,6157.12 h60
  text "394 Total" at 4511.44,6032.8 h60
  text ".Layer_Name" at 577,-858.49 h60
